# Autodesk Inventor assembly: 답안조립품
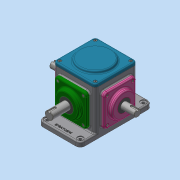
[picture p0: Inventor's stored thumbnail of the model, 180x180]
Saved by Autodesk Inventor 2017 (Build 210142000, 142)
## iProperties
Part Number: 답안조립품
Material: 일반
Document SubType Name: Assembly
Designer: MRC
Author: MRC
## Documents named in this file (16)
- C:\Users\MRC\Desktop\620307V1010\답안조립품.iam
- C:\Users\MRC\Desktop\620307V1010\개스킷.ipt
- C:\Users\MRC\Desktop\620307V1010\메인베벨기어.ipt
- C:\Users\MRC\Desktop\620307V1010\메인축.ipt
- C:\Users\MRC\Desktop\620307V1010\메인커버.ipt
- C:\Users\MRC\Desktop\620307V1010\베어링 6203.ipt
- C:\Users\MRC\Desktop\620307V1010\베어링 6204.ipt
- C:\Users\MRC\Desktop\620307V1010\본체.ipt
- C:\Users\MRC\Desktop\620307V1010\볼트 M4.ipt
- C:\Users\MRC\Desktop\620307V1010\상부커버.ipt
- C:\Users\MRC\Desktop\620307V1010\서브베벨기어.ipt
- C:\Users\MRC\Desktop\620307V1010\서브축.ipt
- C:\Users\MRC\Desktop\620307V1010\서브커버.ipt
- C:\Users\MRC\Desktop\620307V1010\오일 실 17 32 8.ipt
- C:\Users\MRC\Desktop\620307V1010\오일 실 20 35 8.ipt
- C:\Users\MRC\Desktop\620307V1010\키 4x4.ipt
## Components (1 placed, 1 different names)
1. 개스킷:1
